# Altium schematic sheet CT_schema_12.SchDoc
size 146 x 119 mm
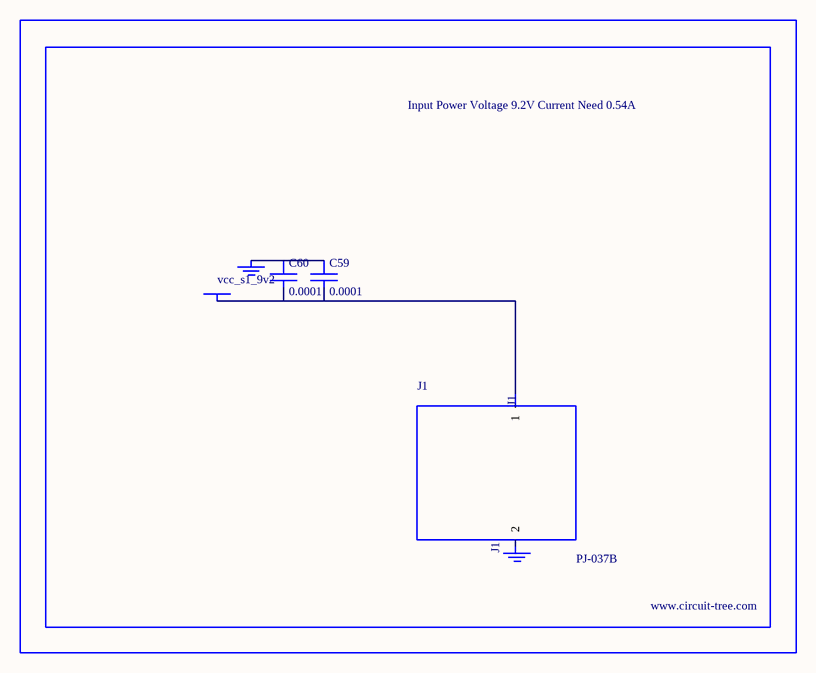
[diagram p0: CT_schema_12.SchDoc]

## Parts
BORDER11  (no value)
C59  0.0001  [EXV-9H]
C60  0.0001  [EXV-9H]
GND_INSTANCE_11_0  (no value)
GND_INSTANCE_11_1  (no value)
J1  PJ-037B  [PJ-037B_PACKAGE]
POWER_INSTANCE_11_0  vcc_s1_9v2

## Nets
NetC59_1: C59.1 C60.1 GND_INSTANCE_11_0.0(GND)
NetC59_2: C59.2 C60.2 J1.1 POWER_INSTANCE_11_0.0(PWR)

Not connected (* = marked no-connect by the designer): GND_INSTANCE_11_1 0(GND); J1 2

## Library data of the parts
BORDER11 = BORDER_PAGE11
C59 C60 = EDK107M035A9HAA
GND_INSTANCE_11_0 GND_INSTANCE_11_1 = GND
POWER_INSTANCE_11_0 = PWR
